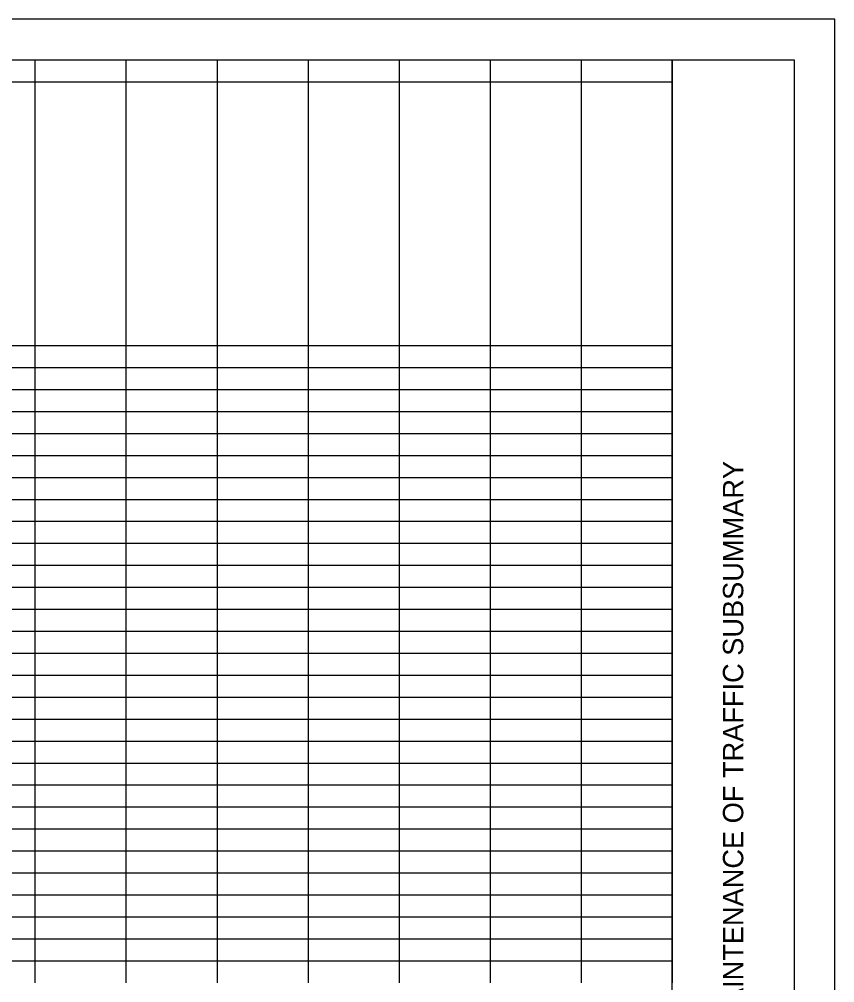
# Model space of a CAD drawing. Extents: x 0 to 34, y 0 to 22.
# Drawn here: x 23.97 to 34, y 10.15 to 22 of the extents above; entities that cross this region are included whole.
import ezdxf

# ---------------------------------------------------------------- set-up
doc = ezdxf.new("R2010")
doc.units = 0
for name, color, linetype in [('Default', 7, 'Continuous'), ('SH_Border', 7, 'Continuous'), ('SH_Cut_Line', 7, 'Continuous'), ('SH_Data', 7, 'Continuous')]:
    doc.layers.add(name, color=color, linetype=linetype)

msp = doc.modelspace()

# ---------------------------------------------------------------- linework, layer by layer
at = {"layer": 'Default'}
for p, q in [((16.325, 21.5), (24.163, 21.5)), ((24.163, 21.5), (25.282, 21.5)), ((24.163, 21.5), (24.163, 21.23)), ((25.282, 21.5), (27.522, 21.5)), ((25.282, 21.5), (25.282, 21.23)), ((26.402, 21.5), (26.402, 21.23)), ((27.522, 21.5), (30.88, 21.5)), ((27.522, 21.5), (27.522, 21.23)), ((28.641, 21.5), (28.641, 21.23)), ((29.761, 21.5), (29.761, 21.23)), ((30.88, 21.5), (32, 21.5)), ((30.88, 21.5), (30.88, 21.23)), ((32, 21.5), (32, 21.23)), ((16.325, 21.23), (24.163, 21.23)), ((24.163, 21.23), (25.282, 21.23)), ((24.163, 21.23), (24.163, 20.959)), ((25.282, 21.23), (27.522, 21.23)), ((25.282, 21.23), (25.282, 20.959)), ((26.402, 21.23), (26.402, 20.959)), ((27.522, 21.23), (30.88, 21.23)), ((27.522, 21.23), (27.522, 20.959)), ((28.641, 21.23), (28.641, 20.959)), ((29.761, 21.23), (29.761, 20.959)), ((30.88, 21.23), (32, 21.23)), ((30.88, 21.23), (30.88, 20.959)), ((32, 21.23), (32, 20.959)), ((24.163, 20.959), (24.163, 20.689)), ((25.282, 20.959), (25.282, 20.689)), ((26.402, 20.959), (26.402, 20.689)), ((27.522, 20.959), (27.522, 20.689)), ((28.641, 20.959), (28.641, 20.689)), ((29.761, 20.959), (29.761, 20.689)), ((30.88, 20.959), (30.88, 20.689)), ((32, 20.959), (32, 20.689)), ((24.163, 20.689), (24.163, 20.419)), ((25.282, 20.689), (25.282, 20.419)), ((26.402, 20.689), (26.402, 20.419)), ((27.522, 20.689), (27.522, 20.419)), ((28.641, 20.689), (28.641, 20.419)), ((29.761, 20.689), (29.761, 20.419)), ((30.88, 20.689), (30.88, 20.419)), ((32, 20.689), (32, 20.419)), ((24.163, 20.419), (24.163, 20.149)), ((25.282, 20.419), (25.282, 20.149)), ((26.402, 20.419), (26.402, 20.149)), ((27.522, 20.419), (27.522, 20.149)), ((28.641, 20.419), (28.641, 20.149)), ((29.761, 20.419), (29.761, 20.149)), ((30.88, 20.419), (30.88, 20.149)), ((32, 20.419), (32, 20.149)), ((24.163, 20.149), (24.163, 19.878)), ((25.282, 20.149), (25.282, 19.878)), ((26.402, 20.149), (26.402, 19.878)), ((27.522, 20.149), (27.522, 19.878)), ((28.641, 20.149), (28.641, 19.878)), ((29.761, 20.149), (29.761, 19.878)), ((30.88, 20.149), (30.88, 19.878)), ((32, 20.149), (32, 19.878)), ((24.163, 19.878), (24.163, 19.608)), ((25.282, 19.878), (25.282, 19.608)), ((26.402, 19.878), (26.402, 19.608)), ((27.522, 19.878), (27.522, 19.608)), ((28.641, 19.878), (28.641, 19.608)), ((29.761, 19.878), (29.761, 19.608)), ((30.88, 19.878), (30.88, 19.608)), ((32, 19.878), (32, 19.608)), ((24.163, 19.608), (24.163, 19.068)), ((25.282, 19.608), (25.282, 19.068)), ((26.402, 19.608), (26.402, 19.068)), ((27.522, 19.608), (27.522, 19.068)), ((28.641, 19.608), (28.641, 19.068)), ((29.761, 19.608), (29.761, 19.068)), ((30.88, 19.608), (30.88, 19.068)), ((32, 19.608), (32, 19.068)), ((24.163, 19.068), (24.163, 18.257)), ((25.282, 19.068), (25.282, 18.257)), ((26.402, 19.068), (26.402, 18.257)), ((27.522, 19.068), (27.522, 18.257)), ((28.641, 19.068), (28.641, 18.257)), ((29.761, 19.068), (29.761, 18.257)), ((30.88, 19.068), (30.88, 18.257)), ((32, 19.068), (32, 18.257)), ((24.163, 18.257), (24.163, 17.987)), ((25.282, 18.257), (25.282, 17.987)), ((26.402, 18.257), (26.402, 17.987)), ((27.522, 18.257), (27.522, 17.987)), ((28.641, 18.257), (28.641, 17.987)), ((29.761, 18.257), (29.761, 17.987)), ((30.88, 18.257), (30.88, 17.987)), ((32, 18.257), (32, 17.987)), ((16.325, 17.987), (24.163, 17.987)), ((24.163, 17.987), (25.282, 17.987)), ((24.163, 17.987), (24.163, 17.446)), ((25.282, 17.987), (27.522, 17.987)), ((25.282, 17.987), (25.282, 17.446)), ((26.402, 17.987), (26.402, 17.446)), ((27.522, 17.987), (30.88, 17.987)), ((27.522, 17.987), (27.522, 17.446)), ((28.641, 17.987), (28.641, 17.446)), ((29.761, 17.987), (29.761, 17.446)), ((30.88, 17.987), (32, 17.987)), ((30.88, 17.987), (30.88, 17.446)), ((32, 17.987), (32, 17.446)), ((16.325, 17.716), (24.163, 17.716)), ((24.163, 17.716), (25.282, 17.716)), ((25.282, 17.716), (27.522, 17.716)), ((27.522, 17.716), (30.88, 17.716)), ((30.88, 17.716), (32, 17.716)), ((16.325, 17.446), (24.163, 17.446)), ((24.163, 17.446), (25.282, 17.446)), ((24.163, 17.446), (24.163, 17.176)), ((25.282, 17.446), (27.522, 17.446)), ((25.282, 17.446), (25.282, 17.176)), ((26.402, 17.446), (26.402, 17.176)), ((27.522, 17.446), (30.88, 17.446)), ((27.522, 17.446), (27.522, 17.176)), ((28.641, 17.446), (28.641, 17.176)), ((29.761, 17.446), (29.761, 17.176)), ((30.88, 17.446), (32, 17.446)), ((30.88, 17.446), (30.88, 17.176)), ((32, 17.446), (32, 17.176)), ((16.325, 17.176), (24.163, 17.176)), ((24.163, 17.176), (25.282, 17.176)), ((24.163, 17.176), (24.163, 16.095)), ((25.282, 17.176), (27.522, 17.176)), ((25.282, 17.176), (25.282, 16.095)), ((26.402, 17.176), (26.402, 16.095)), ((27.522, 17.176), (30.88, 17.176)), ((27.522, 17.176), (27.522, 16.095)), ((28.641, 17.176), (28.641, 16.095)), ((29.761, 17.176), (29.761, 16.095)), ((30.88, 17.176), (32, 17.176)), ((30.88, 17.176), (30.88, 16.095)), ((32, 17.176), (32, 16.095)), ((16.325, 16.906), (24.163, 16.906)), ((24.163, 16.906), (25.282, 16.906)), ((25.282, 16.906), (27.522, 16.906)), ((27.522, 16.906), (30.88, 16.906)), ((30.88, 16.906), (32, 16.906)), ((16.325, 16.635), (24.163, 16.635)), ((24.163, 16.635), (25.282, 16.635)), ((25.282, 16.635), (27.522, 16.635)), ((27.522, 16.635), (30.88, 16.635)), ((30.88, 16.635), (32, 16.635)), ((16.325, 16.365), (24.163, 16.365)), ((24.163, 16.365), (25.282, 16.365)), ((25.282, 16.365), (27.522, 16.365)), ((27.522, 16.365), (30.88, 16.365)), ((30.88, 16.365), (32, 16.365)), ((16.325, 16.095), (24.163, 16.095)), ((24.163, 16.095), (25.282, 16.095)), ((24.163, 16.095), (24.163, 15.825)), ((25.282, 16.095), (27.522, 16.095)), ((25.282, 16.095), (25.282, 15.825)), ((26.402, 16.095), (26.402, 15.825)), ((27.522, 16.095), (30.88, 16.095)), ((27.522, 16.095), (27.522, 15.825)), ((28.641, 16.095), (28.641, 15.825)), ((29.761, 16.095), (29.761, 15.825)), ((30.88, 16.095), (32, 16.095)), ((30.88, 16.095), (30.88, 15.825)), ((32, 16.095), (32, 15.825)), ((16.325, 15.825), (24.163, 15.825)), ((24.163, 15.825), (25.282, 15.825)), ((24.163, 15.825), (24.163, 15.284)), ((25.282, 15.825), (27.522, 15.825)), ((25.282, 15.825), (25.282, 15.284)), ((26.402, 15.825), (26.402, 15.284)), ((27.522, 15.825), (30.88, 15.825)), ((27.522, 15.825), (27.522, 15.284)), ((28.641, 15.825), (28.641, 15.284)), ((29.761, 15.825), (29.761, 15.284)), ((30.88, 15.825), (32, 15.825)), ((30.88, 15.825), (30.88, 15.284)), ((32, 15.825), (32, 15.284)), ((16.325, 15.554), (24.163, 15.554)), ((24.163, 15.554), (25.282, 15.554)), ((25.282, 15.554), (27.522, 15.554)), ((27.522, 15.554), (30.88, 15.554)), ((30.88, 15.554), (32, 15.554)), ((16.325, 15.284), (24.163, 15.284)), ((24.163, 15.284), (25.282, 15.284)), ((24.163, 15.284), (24.163, 14.744)), ((25.282, 15.284), (27.522, 15.284)), ((25.282, 15.284), (25.282, 14.744)), ((26.402, 15.284), (26.402, 14.744)), ((27.522, 15.284), (30.88, 15.284)), ((27.522, 15.284), (27.522, 14.744)), ((28.641, 15.284), (28.641, 14.744)), ((29.761, 15.284), (29.761, 14.744)), ((30.88, 15.284), (32, 15.284)), ((30.88, 15.284), (30.88, 14.744)), ((32, 15.284), (32, 14.744)), ((16.325, 15.014), (24.163, 15.014)), ((24.163, 15.014), (25.282, 15.014)), ((25.282, 15.014), (27.522, 15.014)), ((27.522, 15.014), (30.88, 15.014)), ((30.88, 15.014), (32, 15.014)), ((16.325, 14.744), (24.163, 14.744)), ((24.163, 14.744), (25.282, 14.744)), ((24.163, 14.744), (24.163, 14.473)), ((25.282, 14.744), (27.522, 14.744)), ((25.282, 14.744), (25.282, 14.473)), ((26.402, 14.744), (26.402, 14.473)), ((27.522, 14.744), (30.88, 14.744)), ((27.522, 14.744), (27.522, 14.473)), ((28.641, 14.744), (28.641, 14.473)), ((29.761, 14.744), (29.761, 14.473)), ((30.88, 14.744), (32, 14.744)), ((30.88, 14.744), (30.88, 14.473)), ((32, 14.744), (32, 14.473)), ((16.325, 14.473), (24.163, 14.473)), ((24.163, 14.473), (25.282, 14.473)), ((24.163, 14.473), (24.163, 13.933)), ((25.282, 14.473), (27.522, 14.473)), ((25.282, 14.473), (25.282, 13.933)), ((26.402, 14.473), (26.402, 13.933)), ((27.522, 14.473), (30.88, 14.473)), ((27.522, 14.473), (27.522, 13.933)), ((28.641, 14.473), (28.641, 13.933)), ((29.761, 14.473), (29.761, 13.933)), ((30.88, 14.473), (32, 14.473)), ((30.88, 14.473), (30.88, 13.933)), ((32, 14.473), (32, 13.933)), ((16.325, 14.203), (24.163, 14.203)), ((24.163, 14.203), (25.282, 14.203)), ((25.282, 14.203), (27.522, 14.203)), ((27.522, 14.203), (30.88, 14.203)), ((30.88, 14.203), (32, 14.203)), ((16.325, 13.933), (24.163, 13.933)), ((24.163, 13.933), (25.282, 13.933)), ((24.163, 13.933), (24.163, 13.663)), ((25.282, 13.933), (27.522, 13.933)), ((25.282, 13.933), (25.282, 13.663)), ((26.402, 13.933), (26.402, 13.663)), ((27.522, 13.933), (30.88, 13.933)), ((27.522, 13.933), (27.522, 13.663)), ((28.641, 13.933), (28.641, 13.663)), ((29.761, 13.933), (29.761, 13.663)), ((30.88, 13.933), (32, 13.933)), ((30.88, 13.933), (30.88, 13.663)), ((32, 13.933), (32, 13.663)), ((16.325, 13.663), (24.163, 13.663)), ((24.163, 13.663), (25.282, 13.663)), ((24.163, 13.663), (24.163, 12.852)), ((25.282, 13.663), (27.522, 13.663)), ((25.282, 13.663), (25.282, 12.852)), ((26.402, 13.663), (26.402, 12.852)), ((27.522, 13.663), (30.88, 13.663)), ((27.522, 13.663), (27.522, 12.852)), ((28.641, 13.663), (28.641, 12.852)), ((29.761, 13.663), (29.761, 12.852)), ((30.88, 13.663), (32, 13.663)), ((30.88, 13.663), (30.88, 12.852)), ((32, 13.663), (32, 12.852)), ((16.325, 13.392), (24.163, 13.392)), ((24.163, 13.392), (25.282, 13.392)), ((25.282, 13.392), (27.522, 13.392)), ((27.522, 13.392), (30.88, 13.392)), ((30.88, 13.392), (32, 13.392)), ((16.325, 13.122), (24.163, 13.122)), ((24.163, 13.122), (25.282, 13.122)), ((25.282, 13.122), (27.522, 13.122)), ((27.522, 13.122), (30.88, 13.122)), ((30.88, 13.122), (32, 13.122)), ((16.325, 12.852), (24.163, 12.852)), ((24.163, 12.852), (25.282, 12.852)), ((24.163, 12.852), (24.163, 12.311)), ((25.282, 12.852), (27.522, 12.852)), ((25.282, 12.852), (25.282, 12.311)), ((26.402, 12.852), (26.402, 12.311)), ((27.522, 12.852), (30.88, 12.852)), ((27.522, 12.852), (27.522, 12.311)), ((28.641, 12.852), (28.641, 12.311)), ((29.761, 12.852), (29.761, 12.311)), ((30.88, 12.852), (32, 12.852)), ((30.88, 12.852), (30.88, 12.311)), ((32, 12.852), (32, 12.311)), ((16.325, 12.582), (24.163, 12.582)), ((24.163, 12.582), (25.282, 12.582)), ((25.282, 12.582), (27.522, 12.582)), ((27.522, 12.582), (30.88, 12.582)), ((30.88, 12.582), (32, 12.582)), ((16.325, 12.311), (24.163, 12.311)), ((24.163, 12.311), (25.282, 12.311)), ((24.163, 12.311), (24.163, 11.501)), ((25.282, 12.311), (27.522, 12.311)), ((25.282, 12.311), (25.282, 11.501)), ((26.402, 12.311), (26.402, 11.501)), ((27.522, 12.311), (30.88, 12.311)), ((27.522, 12.311), (27.522, 11.501)), ((28.641, 12.311), (28.641, 11.501)), ((29.761, 12.311), (29.761, 11.501)), ((30.88, 12.311), (32, 12.311)), ((30.88, 12.311), (30.88, 11.501)), ((32, 12.311), (32, 11.501)), ((16.325, 12.041), (24.163, 12.041)), ((24.163, 12.041), (25.282, 12.041)), ((25.282, 12.041), (27.522, 12.041)), ((27.522, 12.041), (30.88, 12.041)), ((30.88, 12.041), (32, 12.041)), ((16.325, 11.771), (24.163, 11.771)), ((24.163, 11.771), (25.282, 11.771)), ((25.282, 11.771), (27.522, 11.771)), ((27.522, 11.771), (30.88, 11.771)), ((30.88, 11.771), (32, 11.771)), ((16.325, 11.501), (24.163, 11.501)), ((24.163, 11.501), (25.282, 11.501)), ((24.163, 11.501), (24.163, 10.96)), ((25.282, 11.501), (27.522, 11.501)), ((25.282, 11.501), (25.282, 10.96)), ((26.402, 11.501), (26.402, 10.96)), ((27.522, 11.501), (30.88, 11.501)), ((27.522, 11.501), (27.522, 10.96)), ((28.641, 11.501), (28.641, 10.96)), ((29.761, 11.501), (29.761, 10.96)), ((30.88, 11.501), (32, 11.501)), ((30.88, 11.501), (30.88, 10.96)), ((32, 11.501), (32, 10.96)), ((16.325, 11.23), (24.163, 11.23)), ((24.163, 11.23), (25.282, 11.23)), ((25.282, 11.23), (27.522, 11.23)), ((27.522, 11.23), (30.88, 11.23)), ((30.88, 11.23), (32, 11.23)), ((16.325, 10.96), (24.163, 10.96)), ((24.163, 10.96), (25.282, 10.96)), ((24.163, 10.96), (24.163, 10.149)), ((25.282, 10.96), (27.522, 10.96)), ((25.282, 10.96), (25.282, 10.149)), ((26.402, 10.96), (26.402, 10.149)), ((27.522, 10.96), (30.88, 10.96)), ((27.522, 10.96), (27.522, 10.149)), ((28.641, 10.96), (28.641, 10.149)), ((29.761, 10.96), (29.761, 10.149)), ((30.88, 10.96), (32, 10.96)), ((30.88, 10.96), (30.88, 10.149)), ((32, 10.96), (32, 10.149)), ((16.325, 10.69), (24.163, 10.69)), ((24.163, 10.69), (25.282, 10.69)), ((25.282, 10.69), (27.522, 10.69)), ((27.522, 10.69), (30.88, 10.69)), ((30.88, 10.69), (32, 10.69)), ((16.325, 10.42), (24.163, 10.42)), ((24.163, 10.42), (25.282, 10.42)), ((25.282, 10.42), (27.522, 10.42)), ((27.522, 10.42), (30.88, 10.42)), ((30.88, 10.42), (32, 10.42))]:
    msp.add_line(p, q, dxfattribs=at)
at = {"layer": 'SH_Border'}
msp.add_line((32, 0.5), (32, 21.5), dxfattribs=at)
msp.add_lwpolyline([(1.5, 21.5), (33.5, 21.5), (33.5, 0.5), (1.5, 0.5)], close=True, dxfattribs=at)
at = {"layer": 'SH_Cut_Line'}
msp.add_lwpolyline([(0, 0), (34, 0), (34, 22), (0, 22)], close=True, dxfattribs=at)

# ---------------------------------------------------------------- texts
at = {"layer": 'SH_Data'}
msp.add_text('MAINTENANCE OF TRAFFIC SUBSUMMARY', height=0.25, rotation=90, dxfattribs=at).set_placement((32.875, 9.584))

doc.saveas('drawing.dxf')
